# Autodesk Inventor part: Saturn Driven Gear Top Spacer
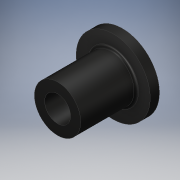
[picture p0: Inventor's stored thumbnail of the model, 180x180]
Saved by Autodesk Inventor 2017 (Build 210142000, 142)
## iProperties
Created: 2016-07
Part Number: Saturn Driven Gear Top Spacer
Material: Generic
Document SubType Name: Modeling
Designer: Stan
Density: 1 g/cm^3
Appearance: Glossy - Black
Author: Stan
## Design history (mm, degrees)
sketch "Sketch1"
  geometry: C1 r 12.7 at (0, 0); 1 further point
  constraints: 1 centre point, 1 coincident
  dimensions: "d0" = 25.4 diameter of C1
extrude "Extrusion1" new body sketch "Sketch1" distance "d1" = 3.175; taper "d2" = 0 deg
sketch "Sketch2"
  geometry: C1 r 7.938 at (0, 0); 1 further point
  constraints: 1 centre point, 1 coincident
  dimensions: "d3" = 15.875 diameter of C1
extrude "Extrusion2" join sketch "Sketch2" distance "d4" = 19.05; taper "d5" = 0 deg
sketch "Sketch3"
  geometry: C1 r 4.445 at (0, 0); 1 further point
  constraints: 1 centre point, 1 coincident
  dimensions: "d6" = 8.89 diameter of C1
extrude "Extrusion3" cut sketch "Sketch3" distance "d7" = 22.225; taper "d8" = 0 deg
fillet "Fillet1" dims "d9" = 0.79375
fillet "Fillet2" dims "d10" = 0.79375
body "Solid1"
